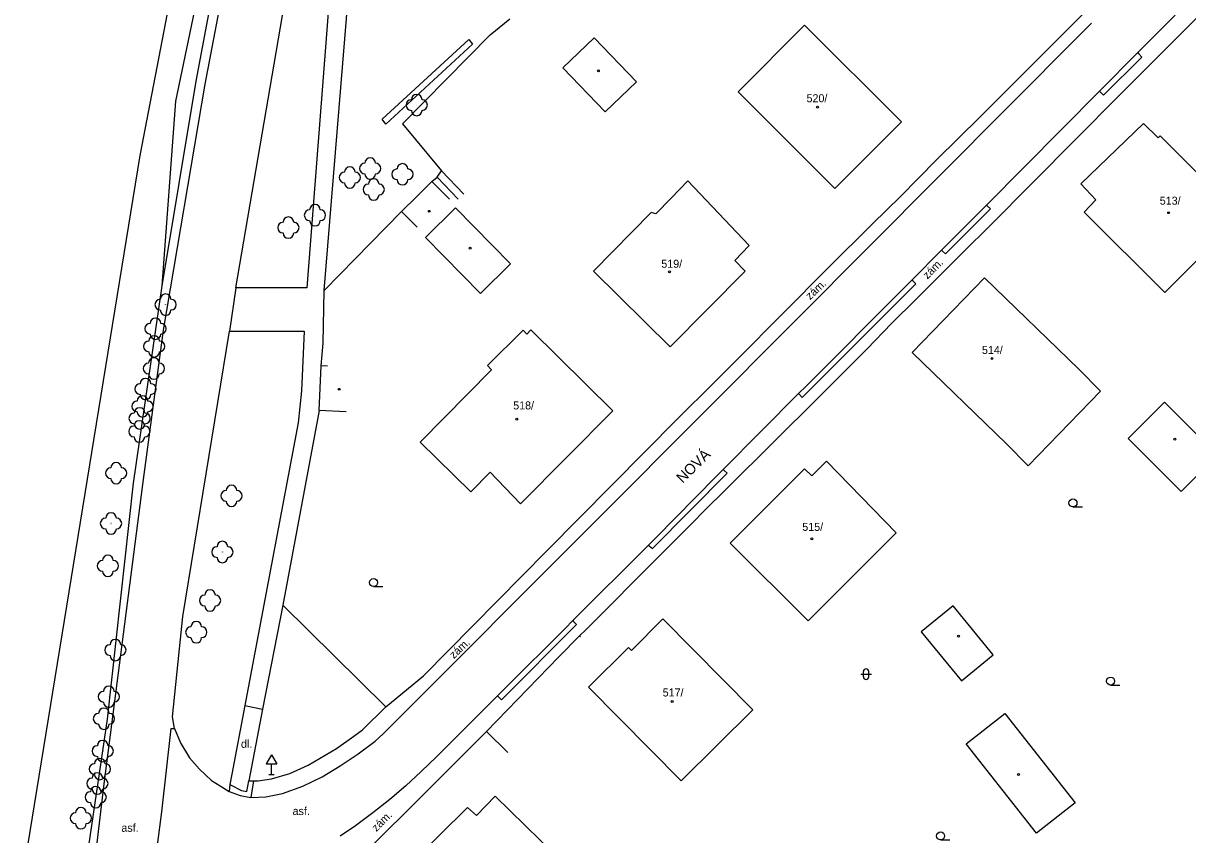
# Model space of a CAD drawing. Extents: x -737488 to -734267, y -1145775 to -1142573.
# Drawn here: x -736668.6 to -736559.5, y -1144381 to -1144304.9 of the extents above; entities that cross this region are included whole.
import ezdxf

# ---------------------------------------------------------------- set-up
doc = ezdxf.new("R2010")
doc.units = 0
for name, color, linetype in [('Vrstva 1', 7, 'Continuous'), ('Vrstva 10', 7, 'Continuous'), ('Vrstva 11', 7, 'Continuous'), ('Vrstva 12', 7, 'Continuous'), ('Vrstva 13', 7, 'Continuous'), ('Vrstva 14', 7, 'Continuous'), ('Vrstva 3', 7, 'Continuous'), ('Vrstva 4', 7, 'Continuous'), ('Vrstva 5', 7, 'Continuous'), ('Vrstva 6', 7, 'Continuous'), ('Vrstva 8', 7, 'Continuous'), ('Vrstva 9', 7, 'Continuous')]:
    doc.layers.add(name, color=color, linetype=linetype)

# ---------------------------------------------------------------- blocks, each defined once
blk = doc.blocks.new('3.130')
at = {"layer": 'Vrstva 1'}
blk.add_circle((0, 0), 0.001, dxfattribs=at)
for centre, start, end in [((-1, 0), 90, 270), ((0, 1), 0, 180), ((1, 0), 270, 90), ((0, -1), 180, 360)]:
    blk.add_arc(centre, 1, start, end, dxfattribs=at)
blk = doc.blocks.new('3.040')
at = {"layer": 'Vrstva 1'}
blk.add_line((0, -0.75), (1.75, -0.75), dxfattribs=at)
blk.add_circle((0, 0), 0.75, dxfattribs=at)
blk = doc.blocks.new('3.160')
at = {"layer": 'Vrstva 1'}
for p, q in [((-1, 0), (1, 0)), ((-0.5, -0.5), (-0.5, 0.5)), ((0.5, -0.5), (0.5, 0.5))]:
    blk.add_line(p, q, dxfattribs=at)
for centre, start, end in [((0, 0.5), 0, 180), ((0, -0.5), 180, 360)]:
    blk.add_arc(centre, 0.5, start, end, dxfattribs=at)
blk = doc.blocks.new('4.020')
at = {"layer": 'Vrstva 1'}
blk.add_circle((0, 0), 0.175, dxfattribs=at)
blk = doc.blocks.new('5.270')
at = {"layer": 'Vrstva 1'}
for p, q in [((0, 3.732), (-1, 2)), ((0, 3.732), (1, 2)), ((-1, 2), (1, 2)), ((-0.5, 0), (0.5, 0)), ((0, 0), (0, 2))]:
    blk.add_line(p, q, dxfattribs=at)

msp = doc.modelspace()

# ---------------------------------------------------------------- linework, layer by layer
at = {"layer": 'Vrstva 10'}
for points in [[(-736634.88, -1144278.99), (-736636.65, -1144278.63), (-736638.72, -1144286.99), (-736642.04, -1144329.72), (-736648.67, -1144329.73)], [(-736640.4, -1144329.99), (-736636.92, -1144287.35), (-736634.88, -1144278.99)], [(-736651.57, -1144310.64), (-736646.51, -1144284.13)], [(-736648.67, -1144329.73), (-736643.56, -1144299.82)], [(-736560.66, -1144304.18), (-736564.18, -1144307.7), (-736564.9, -1144308.42), (-736567, -1144310.56), (-736567.74, -1144311.3), (-736578.33, -1144321.98), (-736578.99, -1144322.65), (-736581.83, -1144325.48), (-736582.56, -1144326.21), (-736585.32, -1144329), (-736586.05, -1144329.73), (-736595.23, -1144338.94), (-736595.94, -1144339.65), (-736603.01, -1144346.76), (-736603.71, -1144347.46), (-736609.32, -1144353.15), (-736610.01, -1144353.84), (-736617.12, -1144360.94), (-736617.8, -1144361.62), (-736623.43, -1144367.26), (-736624.16, -1144367.98), (-736629.85, -1144373.64), (-736631.31, -1144375.07), (-736632.75, -1144376.4), (-736634.24, -1144377.68), (-736635.85, -1144378.95), (-736637.46, -1144380.14), (-736638.91, -1144381.13)], [(-736649.3, -1144376.94), (-736648.29, -1144377.31), (-736647.29, -1144377.5), (-736645.87, -1144377.42), (-736644.31, -1144377.11), (-736642.41, -1144376.43), (-736640.58, -1144375.56), (-736638.89, -1144374.52), (-736637.23, -1144373.42), (-736635.61, -1144372.22), (-736634.86, -1144371.53), (-736614.54, -1144351.17), (-736596.05, -1144332.6), (-736569.58, -1144306.02), (-736568.51, -1144304.92)], [(-736567.74, -1144311.3), (-736567.64, -1144311.4), (-736567.37, -1144311.68), (-736563.77, -1144308.1), (-736564.07, -1144307.81), (-736564.18, -1144307.7)], [(-736655.45, -1144333.69), (-736651.57, -1144310.64)], [(-736582.56, -1144326.21), (-736582.47, -1144326.29), (-736582.17, -1144326.56), (-736577.97, -1144322.33), (-736578.26, -1144322.05), (-736578.33, -1144321.98)], [(-736595.94, -1144339.65), (-736595.88, -1144339.71), (-736595.61, -1144340), (-736584.97, -1144329.36), (-736585.24, -1144329.08), (-736585.32, -1144329)], [(-736648.67, -1144329.73), (-736649.28, -1144333.79)], [(-736657.39, -1144348.15), (-736655.45, -1144333.69)], [(-736653.65, -1144360.53), (-736649.28, -1144333.79)], [(-736649.28, -1144333.79), (-736642.29, -1144333.8), (-736642.54, -1144339.4), (-736642.85, -1144342.4), (-736647.84, -1144368.86), (-736649.06, -1144375.32), (-736649.23, -1144376.29), (-736649.3, -1144376.94)], [(-736610.01, -1144353.84), (-736609.94, -1144353.91), (-736609.65, -1144354.17), (-736602.65, -1144347.11), (-736602.93, -1144346.84), (-736603.01, -1144346.76)], [(-736661.03, -1144376.22), (-736657.39, -1144348.15)], [(-736644.28, -1144359.48), (-736646.17, -1144369.21), (-736647.45, -1144375.93), (-736647.03, -1144375.94), (-736646.59, -1144375.92), (-736645.33, -1144375.74), (-736643.63, -1144375.25), (-736641.89, -1144374.46), (-736639.24, -1144372.9), (-736637.61, -1144371.76), (-736636.81, -1144371.15), (-736634.61, -1144369)], [(-736654.43, -1144371.03), (-736654.63, -1144369.95), (-736653.65, -1144360.53)], [(-736624.16, -1144367.98), (-736624.08, -1144368.06), (-736623.8, -1144368.35), (-736616.77, -1144361.28), (-736617.05, -1144361.01), (-736617.12, -1144360.94)], [(-736647.84, -1144368.86), (-736646.17, -1144369.21)], [(-736657.25, -1144392.68), (-736657.45, -1144392.6), (-736656.44, -1144385.1), (-736655.63, -1144378.83), (-736654.75, -1144371.02), (-736654.43, -1144371.03)], [(-736654.43, -1144371.03), (-736654.38, -1144371.18), (-736653.85, -1144372.44), (-736653.03, -1144373.79), (-736652.1, -1144374.84), (-736650.96, -1144375.89), (-736650.16, -1144376.41), (-736649.3, -1144376.94)], [(-736662.67, -1144390.14), (-736661.03, -1144376.22)], [(-736649.23, -1144376.29), (-736648.16, -1144376.84), (-736647.65, -1144376.93), (-736647.45, -1144375.93)], [(-736647.03, -1144375.94), (-736647.29, -1144377.5)]]:
    msp.add_lwpolyline(points, dxfattribs=at)
at = {"layer": 'Vrstva 11'}
for points in [[(-736657.64, -1144317.34), (-736650.78, -1144281.58)], [(-736668.6, -1144384.7), (-736657.64, -1144317.34)]]:
    msp.add_lwpolyline(points, dxfattribs=at)
at = {"layer": 'Vrstva 12'}
for points in [[(-736654.29, -1144312.24), (-736648.41, -1144283.94)], [(-736652.39, -1144310.37), (-736647.44, -1144283.94)], [(-736655.58, -1144329.54), (-736652.39, -1144310.37)], [(-736655.58, -1144329.54), (-736654.29, -1144312.24)], [(-736658.27, -1144348.03), (-736655.58, -1144329.54)], [(-736660.72, -1144370.16), (-736658.27, -1144348.03)], [(-736663.36, -1144388.18), (-736660.72, -1144370.16)]]:
    msp.add_lwpolyline(points, dxfattribs=at)
at = {"layer": 'Vrstva 4'}
for points in [[(-736630.3, -1144319.77), (-736631.73, -1144321.18)], [(-736631.73, -1144321.18), (-736633.15, -1144322.58)], [(-736640.88, -1144341.24), (-736640.68, -1144337.03)]]:
    msp.add_lwpolyline(points, dxfattribs=at)
at = {"layer": 'Vrstva 5'}
for points in [[(-736601.61, -1144311.36), (-736595.38, -1144305.12)], [(-736595.38, -1144305.12), (-736586.31, -1144314.17)], [(-736618.03, -1144309.12), (-736615.09, -1144306.3)], [(-736615.09, -1144306.3), (-736611.13, -1144310.43)], [(-736614.07, -1144313.25), (-736618.03, -1144309.12)], [(-736611.13, -1144310.43), (-736614.07, -1144313.25)], [(-736592.54, -1144320.41), (-736601.61, -1144311.36)], [(-736586.31, -1144314.17), (-736592.54, -1144320.41)], [(-736563.61, -1144314.32), (-736569.49, -1144319.98)], [(-736562.26, -1144315.67), (-736563.61, -1144314.32)], [(-736562.05, -1144315.49), (-736562.26, -1144315.67)], [(-736554.51, -1144323.03), (-736562.05, -1144315.49)], [(-736628.67, -1144321.42), (-736630.3, -1144319.77)], [(-736606.34, -1144319.7), (-736607.9, -1144321.34)], [(-736600.58, -1144325.76), (-736606.34, -1144319.7)], [(-736569.49, -1144319.98), (-736568.08, -1144321.48)], [(-736607.9, -1144321.34), (-736609.31, -1144322.79)], [(-736568.08, -1144321.48), (-736569.18, -1144322.63)], [(-736631.7, -1144324.06), (-736633.15, -1144322.58)], [(-736630.91, -1144325.03), (-736628.09, -1144322.24)], [(-736628.09, -1144322.24), (-736622.93, -1144327.48)], [(-736609.77, -1144322.67), (-736615.17, -1144328.17)], [(-736609.31, -1144322.79), (-736609.77, -1144322.67)], [(-736569.18, -1144322.63), (-736561.63, -1144330.16)], [(-736561.63, -1144330.16), (-736554.51, -1144323.03)], [(-736625.75, -1144330.26), (-736630.91, -1144325.03)], [(-736601.93, -1144327.17), (-736600.58, -1144325.76)], [(-736600.96, -1144328.17), (-736601.93, -1144327.17)], [(-736622.93, -1144327.48), (-736625.75, -1144330.26)], [(-736615.17, -1144328.17), (-736607.97, -1144335.27)], [(-736607.97, -1144335.27), (-736600.96, -1144328.17)], [(-736578.53, -1144328.78), (-736585.31, -1144335.78)], [(-736569.68, -1144337.36), (-736578.53, -1144328.78)], [(-736621.77, -1144333.71), (-736625.1, -1144337.02)], [(-736621.42, -1144334.06), (-736621.77, -1144333.71)], [(-736621.03, -1144333.68), (-736621.42, -1144334.06)], [(-736613.35, -1144341.26), (-736621.03, -1144333.68)], [(-736585.31, -1144335.78), (-736576.46, -1144344.36)], [(-736640.09, -1144337.06), (-736640.68, -1144337.03)], [(-736625.1, -1144337.02), (-736624.73, -1144337.43)], [(-736624.73, -1144337.43), (-736631.41, -1144344.2)], [(-736567.65, -1144339.43), (-736569.68, -1144337.36)], [(-736574.43, -1144346.4), (-736567.65, -1144339.43)], [(-736638.33, -1144341.36), (-736640.88, -1144341.24)], [(-736621.99, -1144349.99), (-736613.35, -1144341.26)], [(-736561.67, -1144340.44), (-736565.07, -1144343.84)], [(-736556.68, -1144345.42), (-736561.67, -1144340.44)], [(-736631.41, -1144344.2), (-736626.65, -1144348.85)], [(-736576.46, -1144344.36), (-736574.43, -1144346.4)], [(-736565.07, -1144343.84), (-736560.09, -1144348.83)], [(-736560.09, -1144348.83), (-736556.68, -1144345.42)], [(-736602.35, -1144353.65), (-736595.38, -1144346.69)], [(-736595.38, -1144346.69), (-736594.71, -1144347.36)], [(-736594.71, -1144347.36), (-736593.34, -1144345.99)], [(-736593.34, -1144345.99), (-736586.79, -1144352.69)], [(-736626.65, -1144348.85), (-736624.86, -1144347.01)], [(-736624.86, -1144347.01), (-736621.99, -1144349.99)], [(-736586.79, -1144352.69), (-736595.05, -1144360.95)], [(-736595.05, -1144360.95), (-736602.35, -1144353.65)], [(-736581.47, -1144359.54), (-736584.45, -1144361.98)], [(-736577.71, -1144364.12), (-736581.47, -1144359.54)], [(-736611.61, -1144363.72), (-736608.68, -1144360.74)], [(-736608.68, -1144360.74), (-736600.23, -1144369.29)], [(-736584.45, -1144361.98), (-736580.69, -1144366.56)], [(-736615.64, -1144367.17), (-736611.88, -1144363.44)], [(-736611.88, -1144363.44), (-736611.61, -1144363.72)], [(-736580.69, -1144366.56), (-736577.71, -1144364.12)], [(-736606.94, -1144375.94), (-736615.64, -1144367.17)], [(-736600.23, -1144369.29), (-736606.94, -1144375.94)], [(-736580.23, -1144372.46), (-736576.61, -1144369.62)], [(-736576.61, -1144369.62), (-736570.03, -1144378)], [(-736573.65, -1144380.84), (-736580.23, -1144372.46)], [(-736624.38, -1144377.37), (-736626.13, -1144379.19)], [(-736617.34, -1144384.23), (-736624.38, -1144377.37)], [(-736626.96, -1144378.42), (-736634.82, -1144386.19)], [(-736626.13, -1144379.19), (-736626.96, -1144378.42)], [(-736570.03, -1144378), (-736573.65, -1144380.84)]]:
    msp.add_lwpolyline(points, dxfattribs=at)
at = {"layer": 'Vrstva 9'}
for points in [[(-736570.44, -1144305.2), (-736561.27, -1144296.03)], [(-736558.51, -1144304.31), (-736563.14, -1144308.96)], [(-736624.86, -1144306.02), (-736623.02, -1144304.51)], [(-736570.44, -1144305.2), (-736572.62, -1144307.4)], [(-736634.98, -1144313.93), (-736626.85, -1144306.45)], [(-736624.86, -1144306.02), (-736633.06, -1144314.36)], [(-736626.85, -1144306.45), (-736626.51, -1144306.9)], [(-736634.64, -1144314.38), (-736626.51, -1144306.9)], [(-736578.92, -1144313.7), (-736572.62, -1144307.4)], [(-736563.73, -1144309.53), (-736565.94, -1144311.75)], [(-736563.14, -1144308.96), (-736563.73, -1144309.53)], [(-736565.94, -1144311.75), (-736578.06, -1144323.96)], [(-736634.64, -1144314.38), (-736634.98, -1144313.93)], [(-736578.92, -1144313.7), (-736583.03, -1144317.75)], [(-736633.06, -1144314.36), (-736629.41, -1144318.78)], [(-736586.4, -1144321.17), (-736583.03, -1144317.75)], [(-736630.3, -1144319.77), (-736629.82, -1144319.35)], [(-736629.82, -1144319.35), (-736629.41, -1144318.78)], [(-736629.82, -1144319.35), (-736627.86, -1144321.41)], [(-736629.41, -1144318.78), (-736627.31, -1144320.96)], [(-736586.4, -1144321.17), (-736589.02, -1144323.73)], [(-736633.15, -1144322.58), (-736640.4, -1144329.99)], [(-736593.13, -1144327.84), (-736589.02, -1144323.73)], [(-736578.06, -1144323.96), (-736580.47, -1144326.32)], [(-736580.47, -1144326.32), (-736584.93, -1144330.78)], [(-736601.69, -1144336.44), (-736593.13, -1144327.84)], [(-736640.51, -1144334.93), (-736640.4, -1144329.99)], [(-736584.93, -1144330.78), (-736587.23, -1144333.09)], [(-736587.23, -1144333.09), (-736589.51, -1144335.46), (-736594.09, -1144340)], [(-736640.68, -1144337.03), (-736640.51, -1144334.93)], [(-736601.69, -1144336.44), (-736603.89, -1144338.65)], [(-736607.3, -1144342.02), (-736603.89, -1144338.65)], [(-736594.09, -1144340), (-736602.62, -1144348.49)], [(-736640.88, -1144341.24), (-736644.28, -1144359.48)], [(-736619.54, -1144354.38), (-736607.3, -1144342.02)], [(-736602.62, -1144348.49), (-736604.91, -1144350.77)], [(-736604.91, -1144350.77), (-736605.75, -1144351.63)], [(-736605.75, -1144351.63), (-736607.93, -1144353.79)], [(-736634.61, -1144369), (-736631.1, -1144366.1), (-736619.54, -1144354.38)], [(-736607.93, -1144353.79), (-736608.88, -1144354.77)], [(-736608.88, -1144354.77), (-736615.89, -1144361.77), (-736616.48, -1144362.36)], [(-736644.28, -1144359.48), (-736634.61, -1144369)], [(-736618.42, -1144364.33), (-736616.48, -1144362.36)], [(-736616.48, -1144362.36), (-736616.38, -1144362.42)], [(-736618.42, -1144364.33), (-736625.18, -1144371.31)], [(-736625.18, -1144371.31), (-736642.32, -1144388.41)], [(-736623.2, -1144373.28), (-736625.18, -1144371.31)]]:
    msp.add_lwpolyline(points, dxfattribs=at)

# ---------------------------------------------------------------- block references
at = {"layer": 'Vrstva 11', "xscale": 0.5, "yscale": 0.5}
for p in [(-736631.73, -1144312.6), (-736638, -1144319.39), (-736636.09, -1144318.55), (-736633.07, -1144319.09), (-736635.76, -1144320.52), (-736641.27, -1144322.93), (-736643.76, -1144324.09), (-736655.26, -1144331.31), (-736656.21, -1144333.56), (-736656.33, -1144335.22), (-736656.36, -1144337.29), (-736657.14, -1144339.22), (-736657.43, -1144340.84), (-736657.7, -1144341.97), (-736657.72, -1144343.19), (-736659.9, -1144347.1), (-736649.09, -1144349.23), (-736660.38, -1144351.82), (-736649.94, -1144354.49), (-736660.67, -1144355.79), (-736651.1, -1144359.03), (-736652.39, -1144362.01), (-736659.97, -1144363.68), (-736660.58, -1144368.05), (-736661.04, -1144370.11), (-736661.16, -1144373.14), (-736661.42, -1144374.83), (-736661.66, -1144376.19), (-736661.81, -1144377.47), (-736663.2, -1144379.44)]:
    msp.add_blockref('3.130', p, dxfattribs=at)
at = {"layer": 'Vrstva 3', "xscale": 0.5, "yscale": 0.5}
for name, p in [('3.040', (-736570.23, -1144349.89)), ('3.040', (-736635.78, -1144357.35)), ('3.160', (-736589.62, -1144365.94)), ('3.040', (-736566.71, -1144366.59)), ('3.040', (-736582.64, -1144381.1))]:
    msp.add_blockref(name, p, dxfattribs=at)
at = {"layer": 'Vrstva 8', "xscale": 0.5, "yscale": 0.5}
for p in [(-736614.71, -1144309.39), (-736594.17, -1144312.8), (-736630.55, -1144322.56), (-736561.27, -1144322.69), (-736626.72, -1144326.01), (-736608.04, -1144328.23), (-736577.82, -1144336.35), (-736638.99, -1144339.24), (-736622.36, -1144342.05), (-736560.69, -1144343.91), (-736594.71, -1144353.25), (-736580.96, -1144362.38), (-736607.79, -1144368.5), (-736575.33, -1144375.34)]:
    msp.add_blockref('4.020', p, dxfattribs=at)
at = {"layer": 'Vrstva 9', "xscale": 0.5, "yscale": 0.5}
msp.add_blockref('5.270', (-736645.35, -1144375.35), dxfattribs=at)

# ---------------------------------------------------------------- texts
at = {"layer": 'Vrstva 13'}
msp.add_text('NOVÁ', height=1, rotation=44.716, dxfattribs=at).set_placement((-736606.81, -1144348.11))
at = {"layer": 'Vrstva 14'}
for rotation, p in [(44.933, (-736583.87, -1144328.96)), (43.038, (-736594.87, -1144330.9)), (43.038, (-736628.26, -1144364.54)), (44.933, (-736635.51, -1144380.74))]:
    msp.add_text('zám.', height=0.75, rotation=rotation, dxfattribs=at).set_placement(p)
for s, p in [('dl.', (-736648.2, -1144372.84)), ('asf.', (-736643.36, -1144379.14)), ('asf.', (-736659.41, -1144380.71))]:
    msp.add_text(s, height=0.75, dxfattribs=at).set_placement(p)
at = {"layer": 'Vrstva 6'}
for s, p in [('520/', (-736595.2, -1144312.34)), ('513/', (-736562.1, -1144321.94)), ('519/', (-736608.81, -1144327.85)), ('514/', (-736578.76, -1144335.93)), ('518/', (-736622.69, -1144341.13)), ('515/', (-736595.6, -1144352.51)), ('517/', (-736608.68, -1144368.03))]:
    msp.add_text(s, height=0.75, dxfattribs=at).set_placement(p)

doc.saveas('drawing.dxf')
